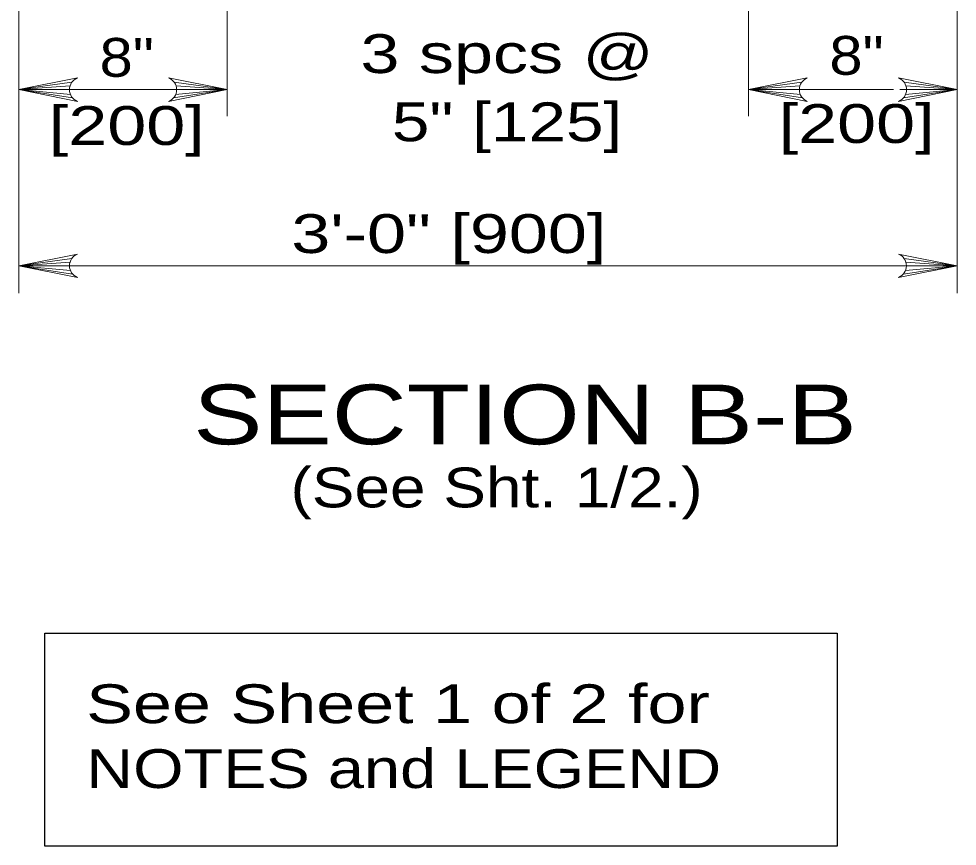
# Model space of a CAD drawing. Extents: x 339.1 to 373.1, y 1412.7 to 1456.7.
# Drawn here: x 357.865 to 361.635, y 1424.252 to 1427.578 of the extents above; entities that cross this region are included whole.
import ezdxf
from ezdxf.enums import TextEntityAlignment as Align

# ---------------------------------------------------------------- set-up
doc = ezdxf.new("R2010")
doc.units = 0
doc.header["$LTSCALE"] = 0.062
doc.layers.add('1', color=7, linetype='Continuous', lineweight=13)

msp = doc.modelspace()

# ---------------------------------------------------------------- linework, layer by layer
at = {"layer": '1'}
for p, q in [((358.703, 1429.706), (358.703, 1427.18717)), ((360.79708, 1427.18717), (360.79708, 1429.64608)), ((357.86533, 1428.61708), (357.86533, 1426.47592)), ((361.63475, 1428.61708), (361.63475, 1426.47592)), ((358.07867, 1427.32317), (357.86533, 1427.29333)), ((358.48975, 1427.32317), (358.703, 1427.29333)), ((361.01042, 1427.32317), (360.79708, 1427.29333)), ((361.42167, 1427.32317), (361.63492, 1427.29333)), ((358.07142, 1427.30842), (357.86533, 1427.29333)), ((357.86533, 1427.29333), (358.50042, 1427.29333)), ((358.06925, 1427.29333), (357.86533, 1427.29333)), ((358.073, 1427.27417), (357.86533, 1427.29333)), ((358.08117, 1427.26033), (357.86533, 1427.29333)), ((358.43158, 1427.29333), (358.703, 1427.29333)), ((358.48717, 1427.26033), (358.703, 1427.29333)), ((358.49533, 1427.27417), (358.703, 1427.29333)), ((358.49692, 1427.30842), (358.703, 1427.29333)), ((358.49917, 1427.29333), (358.703, 1427.29333)), ((361.00317, 1427.30842), (360.79708, 1427.29333)), ((360.79708, 1427.29333), (361.37867, 1427.29333)), ((361.001, 1427.29333), (360.79708, 1427.29333)), ((361.00475, 1427.27417), (360.79708, 1427.29333)), ((361.01292, 1427.26033), (360.79708, 1427.29333)), ((361.4045, 1427.29333), (361.63492, 1427.29333)), ((361.41917, 1427.26033), (361.63492, 1427.29333)), ((361.42733, 1427.27417), (361.63492, 1427.29333)), ((361.42892, 1427.30842), (361.63492, 1427.29333)), ((361.43108, 1427.29333), (361.63492, 1427.29333)), ((358.07867, 1426.61517), (357.86533, 1426.58533)), ((361.4215, 1426.61517), (361.63475, 1426.58533)), ((358.07142, 1426.60042), (357.86533, 1426.58533)), ((358.06925, 1426.58533), (357.86533, 1426.58533)), ((358.073, 1426.56617), (357.86533, 1426.58533)), ((358.08117, 1426.55233), (357.86533, 1426.58533)), ((361.41892, 1426.55233), (361.63475, 1426.58533)), ((361.42708, 1426.56617), (361.63475, 1426.58533)), ((361.42867, 1426.60042), (361.63475, 1426.58533)), ((361.43092, 1426.58533), (361.63475, 1426.58533))]:
    msp.add_line(p, q, dxfattribs=at)
for points in [[(358.10092, 1427.24625), (357.86533, 1427.29333), (358.10092, 1427.34042)], [(358.46742, 1427.24625), (358.703, 1427.29333), (358.46742, 1427.34042)], [(361.03267, 1427.24625), (360.79708, 1427.29333), (361.03267, 1427.34042)], [(361.39933, 1427.24625), (361.63492, 1427.29333), (361.39933, 1427.34042)], [(358.10092, 1426.53825), (357.86533, 1426.58533), (358.10092, 1426.63242)], [(361.39917, 1426.53825), (361.63475, 1426.58533), (361.39917, 1426.63242)], [(357.86533, 1426.58533), (360.15192, 1426.58533), (361.63475, 1426.58533)]]:
    msp.add_lwpolyline(points, dxfattribs=at)
at = {"layer": '1', "lineweight": 25}
msp.add_lwpolyline([(357.9695, 1425.10867), (361.15325, 1425.10867), (361.15325, 1424.25225), (357.9695, 1424.25225)], close=True, dxfattribs=at)
at = {"layer": '1'}
for centre, start, end in [((358.11996, 1427.29338), 112.08782, 247.91395), ((358.44838, 1427.29338), 292.08605, 67.91218), ((361.05171, 1427.29338), 112.08782, 247.91395), ((361.38034, 1427.29338), 292.08605, 67.91218), ((358.11996, 1426.58539), 112.08782, 247.91395), ((361.38013, 1426.58539), 292.08605, 67.91218)]:
    msp.add_arc(centre, 0.05085, start, end, dxfattribs=at)

# ---------------------------------------------------------------- texts
for s, width, p in [('3 spcs @', 1.35, (359.82679, 1427.36008)), ('8"', 1.15, (361.23054, 1427.35308)), ('8"', 1.15, (358.29912, 1427.34508)), ('5" [125]', 1.3, (359.82683, 1427.08608)), ('[200]', 1.35, (361.23062, 1427.07908)), ('[200]', 1.35, (358.29921, 1427.07108))]:
    msp.add_text(s, height=0.156, dxfattribs=dict(at, width=width)).set_placement(p, align=Align.CENTER)
for s, height, width, p in [('3\'-0" [900]', 0.156, 1.35, (358.96008, 1426.63675)), ('SECTION B-B', 0.24, 1.3, (358.56583, 1425.86767)), ('(See Sht. 1/2.)', 0.16, 1.2, (358.95692, 1425.61425)), ('See Sheet 1 of 2 for ', 0.156, 1.35, (358.13617, 1424.747)), ('NOTES and LEGEND', 0.156, 1.25, (358.13617, 1424.48633))]:
    msp.add_text(s, height=height, dxfattribs=dict(at, width=width)).set_placement(p)

doc.saveas('drawing.dxf')
